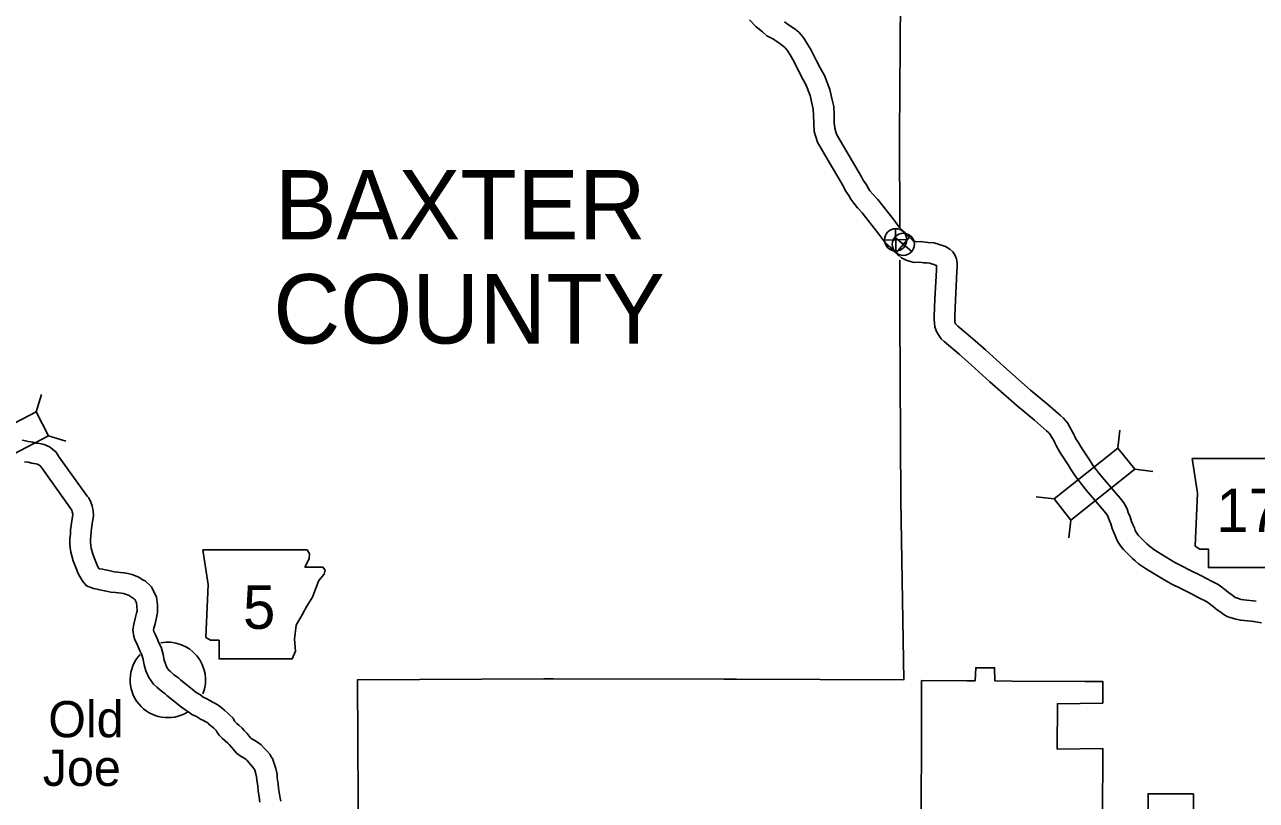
# Model space of a CAD drawing. Extents: x 1377389 to 1380723, y 1168351 to 1170484.
# Drawn here: x 1377653.7 to 1377833.2, y 1170024.2 to 1170137.2 of the extents above; entities that cross this region are included whole.
import ezdxf

# ---------------------------------------------------------------- set-up
doc = ezdxf.new("R2010")
doc.units = 0
doc.layers.add('B_Fill', color=7, linetype='Continuous')
doc.layers.add('Default', color=7, linetype='Continuous')

msp = doc.modelspace()

# ---------------------------------------------------------------- linework, layer by layer
at = {"layer": 'B_Fill'}
for p, q in [((1377780.69, 1170104.22), (1377780.62, 1170107.47)), ((1377779.03, 1170105.81), (1377782.28, 1170105.88)), ((1377780.52, 1170106.25), (1377783.01, 1170104.16)), ((1377780.72, 1170103.96), (1377782.81, 1170106.45)), ((1377655.35, 1170080.79), (1377656.14, 1170083.31)), ((1377813.05, 1170075.51), (1377813.35, 1170078.13)), ((1377657.18, 1170077.28), (1377659.7, 1170076.49)), ((1377815.51, 1170072.41), (1377818.13, 1170072.11)), ((1377803.74, 1170068.12), (1377801.12, 1170068.42)), ((1377806.21, 1170065.02), (1377805.91, 1170062.4))]:
    msp.add_line(p, q, dxfattribs=at)
for points in [[(1377781.38, 1170180.66), (1377781.34, 1170174.2), (1377781.43, 1170147.52), (1377781.22, 1170121.07), (1377781.24, 1170107.61)], [(1377759.33, 1170137.9), (1377760.3, 1170136.87), (1377761.24, 1170136.14), (1377761.9, 1170135.56), (1377762.83, 1170135.08), (1377763.36, 1170134.68), (1377763.76, 1170134.44), (1377764.26, 1170134.09), (1377764.47, 1170133.93), (1377764.57, 1170133.81), (1377764.83, 1170133.5), (1377765.26, 1170132.79), (1377765.69, 1170132.12), (1377766.49, 1170130.5), (1377766.98, 1170129.51), (1377767.57, 1170128.48), (1377768.19, 1170126.88), (1377768.44, 1170125.77), (1377768.65, 1170124.88), (1377768.67, 1170124.02), (1377768.71, 1170122.78), (1377768.8, 1170121.61), (1377769.25, 1170120.06), (1377769.98, 1170118.82), (1377773.04, 1170113.61), (1377773.35, 1170113), (1377773.84, 1170112.3), (1377774.12, 1170111.77), (1377774.54, 1170111.17), (1377775.1, 1170110.53), (1377775.79, 1170109.76), (1377778.04, 1170106.89), (1377778.78, 1170105.89), (1377779.23, 1170105.31), (1377779.92, 1170104.72), (1377780.25, 1170104.35), (1377780.58, 1170104.07), (1377780.97, 1170103.68), (1377781.21, 1170103.49)], [(1377764.43, 1170137.63), (1377765.04, 1170137.18), (1377765.4, 1170136.95), (1377766.06, 1170136.5), (1377766.56, 1170136.09), (1377766.86, 1170135.74), (1377767.28, 1170135.24), (1377767.8, 1170134.38), (1377768.31, 1170133.6), (1377769.17, 1170131.83), (1377769.63, 1170130.93), (1377770.28, 1170129.77), (1377771.06, 1170127.77), (1377771.37, 1170126.44), (1377771.64, 1170125.26), (1377771.67, 1170124.11), (1377771.71, 1170122.95), (1377771.77, 1170122.14), (1377772.03, 1170121.26), (1377772.57, 1170120.34), (1377775.68, 1170115.05), (1377775.93, 1170114.54), (1377776.4, 1170113.88), (1377776.69, 1170113.33), (1377776.91, 1170113.01), (1377777.33, 1170112.52), (1377778.08, 1170111.71), (1377780.43, 1170108.71), (1377781.17, 1170107.71), (1377781.31, 1170107.53)], [(1377781.33, 1170107.5), (1377781.41, 1170107.39), (1377782.02, 1170106.87), (1377782.36, 1170106.49), (1377782.6, 1170106.28), (1377782.98, 1170105.92), (1377783.18, 1170105.75), (1377783.37, 1170105.65), (1377783.48, 1170105.61), (1377783.67, 1170105.56), (1377784.22, 1170105.61), (1377785.02, 1170105.49), (1377785.36, 1170105.47), (1377786.21, 1170105.39), (1377786.74, 1170105.24), (1377787.01, 1170105.15)], [(1377787, 1170105.16), (1377787.9, 1170104.87), (1377788.55, 1170104.5), (1377788.97, 1170104.1), (1377789.28, 1170103.65), (1377789.52, 1170103.06), (1377789.62, 1170102.5), (1377789.63, 1170101.89), (1377789.58, 1170101.25), (1377789.37, 1170097.04), (1377789.27, 1170094.69), (1377789.28, 1170094.28), (1377789.29, 1170093.92), (1377789.3, 1170093.82), (1377789.33, 1170093.75), (1377789.4, 1170093.62), (1377789.53, 1170093.45), (1377789.73, 1170093.27), (1377791.86, 1170091.47), (1377793.73, 1170089.8), (1377796.4, 1170087.39), (1377800.3, 1170083.96), (1377802.85, 1170081.86), (1377804.67, 1170080.25), (1377805.11, 1170079.84), (1377805.38, 1170079.56), (1377805.68, 1170079.16), (1377805.98, 1170078.67), (1377806.29, 1170078.13), (1377806.56, 1170077.6), (1377806.76, 1170077.19), (1377806.94, 1170076.83), (1377807.14, 1170076.51), (1377807.34, 1170076.2), (1377807.59, 1170075.79), (1377807.94, 1170075.26), (1377808.32, 1170074.67), (1377808.79, 1170073.94), (1377809.14, 1170073.38), (1377809.46, 1170072.92), (1377809.83, 1170072.45), (1377810.12, 1170072.06), (1377810.79, 1170071.22), (1377813.37, 1170068.2), (1377813.9, 1170067.53), (1377814.17, 1170067.09), (1377814.38, 1170066.63), (1377814.57, 1170066.13), (1377814.83, 1170065.46), (1377815.05, 1170064.8), (1377815.21, 1170064.39), (1377815.45, 1170063.87), (1377815.58, 1170063.49), (1377815.69, 1170063.27), (1377815.8, 1170063.09), (1377815.91, 1170062.94), (1377816.04, 1170062.78), (1377816.27, 1170062.56), (1377816.75, 1170062.09), (1377817.27, 1170061.57), (1377817.6, 1170061.25), (1377817.85, 1170061.04), (1377818.31, 1170060.73), (1377818.84, 1170060.37), (1377821.36, 1170058.85), (1377822.21, 1170058.39), (1377823.65, 1170057.66), (1377825.16, 1170056.94), (1377826.06, 1170056.44), (1377826.59, 1170056.18), (1377827.1, 1170055.9), (1377827.55, 1170055.65), (1377827.94, 1170055.43), (1377828.45, 1170055.06), (1377828.82, 1170054.76), (1377829.21, 1170054.43), (1377829.46, 1170054.25), (1377829.86, 1170053.96), (1377830.14, 1170053.75), (1377830.18, 1170053.73), (1377830.64, 1170053.6), (1377831.03, 1170053.46), (1377831.43, 1170053.38), (1377833.19, 1170053.21)], [(1377781.29, 1170103.42), (1377781.5, 1170103.24), (1377782.2, 1170102.88), (1377782.61, 1170102.74), (1377783.37, 1170102.53), (1377784.11, 1170102.59), (1377784.74, 1170102.49), (1377785.16, 1170102.48), (1377785.66, 1170102.43), (1377785.88, 1170102.37), (1377786.07, 1170102.3)], [(1377781.25, 1170102.87), (1377781.27, 1170094.83), (1377781.39, 1170067.86), (1377781.87, 1170041.74), (1377757.45, 1170041.84), (1377755.62, 1170041.82), (1377730.78, 1170041.9), (1377729.39, 1170041.87), (1377702.21, 1170041.75), (1377702.36, 1170015.31), (1377702.37, 1170011.92)], [(1377786.09, 1170102.3), (1377786.63, 1170102.13), (1377786.63, 1170101.97), (1377786.59, 1170101.44), (1377786.37, 1170097.18), (1377786.27, 1170094.71), (1377786.29, 1170094.2), (1377786.3, 1170093.76), (1377786.35, 1170093.16), (1377786.6, 1170092.49), (1377786.88, 1170091.98), (1377787.31, 1170091.42), (1377787.75, 1170091.02), (1377789.9, 1170089.2), (1377791.73, 1170087.57), (1377794.4, 1170085.15), (1377798.35, 1170081.67), (1377800.91, 1170079.57), (1377802.66, 1170078.03), (1377803, 1170077.71), (1377803.08, 1170077.63), (1377803.2, 1170077.47), (1377803.39, 1170077.15), (1377803.65, 1170076.69), (1377803.88, 1170076.26), (1377804.06, 1170075.87), (1377804.32, 1170075.36), (1377804.61, 1170074.9), (1377804.8, 1170074.6), (1377805.07, 1170074.17), (1377805.43, 1170073.63), (1377805.8, 1170073.04), (1377806.26, 1170072.33), (1377806.64, 1170071.73), (1377807.05, 1170071.14), (1377807.44, 1170070.64), (1377807.73, 1170070.24), (1377808.47, 1170069.31), (1377811.06, 1170066.29), (1377811.43, 1170065.82), (1377811.52, 1170065.67), (1377811.62, 1170065.45), (1377811.77, 1170065.06), (1377812.01, 1170064.46), (1377812.22, 1170063.79), (1377812.45, 1170063.21), (1377812.67, 1170062.74), (1377812.8, 1170062.36), (1377813.05, 1170061.83), (1377813.31, 1170061.4), (1377813.56, 1170061.07), (1377813.86, 1170060.72), (1377814.18, 1170060.41), (1377814.64, 1170059.96), (1377815.17, 1170059.43), (1377815.56, 1170059.05), (1377816.03, 1170058.64), (1377816.64, 1170058.24), (1377817.21, 1170057.84), (1377819.87, 1170056.25), (1377820.82, 1170055.73), (1377822.33, 1170054.97), (1377823.78, 1170054.27), (1377824.67, 1170053.78), (1377825.22, 1170053.51), (1377825.67, 1170053.27), (1377826.09, 1170053.03), (1377826.31, 1170052.91), (1377826.61, 1170052.68), (1377826.92, 1170052.44), (1377827.34, 1170052.08), (1377827.69, 1170051.82), (1377828.08, 1170051.55), (1377828.53, 1170051.2), (1377829.08, 1170050.92), (1377829.75, 1170050.73), (1377830.22, 1170050.57), (1377830.97, 1170050.41), (1377832.91, 1170050.23)], [(1377653.33, 1170076.64), (1377653.79, 1170076.55), (1377654.19, 1170076.47), (1377654.86, 1170076.38), (1377655.36, 1170076.23), (1377655.84, 1170076.17), (1377656.55, 1170076), (1377657.32, 1170075.66), (1377658.23, 1170074.94), (1377658.73, 1170074.2), (1377662.81, 1170068.48), (1377663.05, 1170068.26), (1377663.36, 1170067.64), (1377663.53, 1170067.08), (1377663.56, 1170066.78), (1377663.67, 1170066.39), (1377663.73, 1170065.63), (1377663.59, 1170064.78), (1377663.45, 1170063.77), (1377663.38, 1170063.29), (1377663.36, 1170062.73), (1377663.29, 1170062.14), (1377663.29, 1170061.72), (1377663.32, 1170061.3), (1377663.38, 1170060.94), (1377663.61, 1170060.04), (1377664.08, 1170058.92), (1377664.24, 1170058.46), (1377664.37, 1170058.18), (1377664.51, 1170057.94), (1377664.51, 1170057.94), (1377664.55, 1170057.92), (1377665.03, 1170057.85), (1377665.49, 1170057.74), (1377665.97, 1170057.64), (1377666.74, 1170057.49), (1377667.25, 1170057.42), (1377667.66, 1170057.38), (1377668.15, 1170057.34), (1377668.75, 1170057.24), (1377669.36, 1170057.06), (1377669.95, 1170056.82), (1377670.34, 1170056.69), (1377670.99, 1170056.25), (1377671.24, 1170056.14), (1377672.17, 1170055.29), (1377672.59, 1170054.48), (1377672.91, 1170053.83), (1377673.04, 1170052.68), (1377673.07, 1170051.52), (1377672.93, 1170050.8), (1377672.7, 1170049.9), (1377672.53, 1170049.24), (1377672.49, 1170049.03), (1377672.54, 1170048.74), (1377672.55, 1170048.69), (1377672.75, 1170048.29), (1377672.99, 1170047.75), (1377673.27, 1170047.12), (1377673.58, 1170046.47), (1377673.89, 1170045.41), (1377674.05, 1170044.58), (1377674.2, 1170044.05), (1377674.42, 1170043.54), (1377674.7, 1170043.14), (1377674.93, 1170042.94), (1377675.46, 1170042.47), (1377676.1, 1170042.02), (1377676.42, 1170041.71), (1377678.38, 1170040.13), (1377678.69, 1170039.9), (1377679.33, 1170039.53), (1377679.7, 1170039.23), (1377680.15, 1170039.01), (1377680.76, 1170038.65), (1377681.19, 1170038.44)], [(1377653.68, 1170073.52), (1377654.22, 1170073.44), (1377654.76, 1170073.28), (1377655.3, 1170073.22), (1377655.58, 1170073.15), (1377655.77, 1170073.06), (1377656.01, 1170072.87), (1377656.27, 1170072.49), (1377660.55, 1170066.47), (1377660.58, 1170066.45), (1377660.61, 1170066.2), (1377660.7, 1170065.87), (1377660.71, 1170065.76), (1377660.62, 1170065.23), (1377660.49, 1170064.21), (1377660.38, 1170063.59), (1377660.36, 1170062.95), (1377660.29, 1170062.31), (1377660.29, 1170061.61), (1377660.34, 1170060.96), (1377660.44, 1170060.33), (1377660.76, 1170059.07), (1377661.27, 1170057.86), (1377661.45, 1170057.32), (1377661.71, 1170056.79), (1377662.05, 1170056.2), (1377662.7, 1170055.45), (1377663.71, 1170055.02), (1377664.47, 1170054.9), (1377664.83, 1170054.82), (1377665.36, 1170054.7), (1377666.27, 1170054.52), (1377666.92, 1170054.44), (1377667.37, 1170054.4), (1377667.77, 1170054.36), (1377668.09, 1170054.31), (1377668.37, 1170054.23), (1377668.92, 1170054), (1377668.99, 1170053.98), (1377669.54, 1170053.6), (1377669.61, 1170053.58), (1377669.75, 1170053.44), (1377669.91, 1170053.13), (1377669.99, 1170052.97), (1377670.05, 1170052.47), (1377670.07, 1170051.77), (1377670, 1170051.46), (1377669.8, 1170050.66), (1377669.59, 1170049.86), (1377669.46, 1170049.02), (1377669.61, 1170048.03), (1377669.77, 1170047.56), (1377670.03, 1170047.03), (1377670.25, 1170046.53), (1377670.55, 1170045.85), (1377670.77, 1170045.39), (1377670.97, 1170044.71), (1377671.12, 1170043.9), (1377671.36, 1170043.06), (1377671.79, 1170042.06), (1377672.46, 1170041.11), (1377672.95, 1170040.68), (1377673.61, 1170040.11), (1377674.18, 1170039.7), (1377674.43, 1170039.46), (1377676.53, 1170037.76), (1377677.03, 1170037.39), (1377677.64, 1170037.04), (1377678.08, 1170036.69), (1377678.72, 1170036.37), (1377679.34, 1170036), (1377679.87, 1170035.75)], [(1377833.98, 1170050.06), (1377832.83, 1170050.24)], [(1377810.79, 1170018.55), (1377810.82, 1170025.15), (1377810.83, 1170028.2), (1377810.84, 1170031.75), (1377804.22, 1170031.64), (1377804.24, 1170038.24), (1377810.85, 1170038.35), (1377810.86, 1170041.48), (1377808.21, 1170041.49), (1377797.65, 1170041.55), (1377795.12, 1170041.57), (1377795.08, 1170043.5), (1377792.33, 1170043.5), (1377792.24, 1170041.59), (1377791.05, 1170041.59), (1377784.44, 1170041.63), (1377784.4, 1170031.33), (1377784.36, 1170024.73), (1377784.32, 1170018.13)], [(1377681.23, 1170038.42), (1377681.75, 1170038.14), (1377682.26, 1170037.8), (1377682.62, 1170037.45), (1377682.85, 1170037.27), (1377683.32, 1170036.89), (1377683.62, 1170036.58), (1377684.07, 1170036.13), (1377684.29, 1170035.7), (1377684.31, 1170035.67), (1377684.6, 1170035.36), (1377684.89, 1170035.11), (1377685.38, 1170034.68), (1377685.71, 1170034.35), (1377686.12, 1170033.89), (1377686.41, 1170033.54), (1377686.67, 1170033.24), (1377686.81, 1170033.13), (1377687.26, 1170032.87), (1377687.61, 1170032.64), (1377688.15, 1170032.26), (1377688.6, 1170031.76), (1377688.88, 1170031.48), (1377689.48, 1170030.87), (1377689.59, 1170030.54), (1377689.81, 1170030.28), (1377690.06, 1170029.55), (1377690.3, 1170028.82), (1377690.49, 1170027.99), (1377690.51, 1170027.46), (1377690.65, 1170026.57), (1377690.7, 1170025.93), (1377690.85, 1170025.06), (1377690.92, 1170024.47), (1377691.03, 1170024.05)], [(1377679.82, 1170035.77), (1377680.21, 1170035.57), (1377680.37, 1170035.46), (1377680.64, 1170035.19), (1377680.98, 1170034.92), (1377681.29, 1170034.67), (1377681.47, 1170034.49), (1377681.61, 1170034.35), (1377681.76, 1170034.05), (1377682.06, 1170033.68), (1377682.52, 1170033.2), (1377682.91, 1170032.86), (1377683.33, 1170032.49), (1377683.52, 1170032.29), (1377683.85, 1170031.92), (1377684.13, 1170031.59), (1377684.59, 1170031.07), (1377685.12, 1170030.64), (1377685.68, 1170030.32), (1377685.91, 1170030.17), (1377686.07, 1170030.05), (1377687.16, 1170028.77), (1377687.22, 1170028.59), (1377687.4, 1170028.02), (1377687.5, 1170027.6), (1377687.52, 1170027.16), (1377687.67, 1170026.22), (1377687.72, 1170025.55), (1377687.88, 1170024.62), (1377687.97, 1170023.91)], [(1377824.05, 1170018.52), (1377824.07, 1170025.12), (1377817.44, 1170025.13), (1377817.42, 1170018.54)]]:
    msp.add_lwpolyline(points, dxfattribs=at)
for points in [[(1377655.35, 1170080.79), (1377644.81, 1170075.31), (1377646.64, 1170071.8), (1377657.18, 1170077.28)], [(1377813.05, 1170075.51), (1377803.74, 1170068.12), (1377806.21, 1170065.02), (1377815.51, 1170072.41)], [(1377823.87, 1170073.99), (1377824.63, 1170068.91), (1377824.29, 1170061.22), (1377824.97, 1170060.79), (1377826.24, 1170060.79), (1377826.24, 1170058.09), (1377836.9, 1170058.09), (1377837.4, 1170059.19), (1377837.23, 1170060.96), (1377837.49, 1170062.99), (1377838.42, 1170064.6), (1377839.01, 1170065.78), (1377839.86, 1170067.05), (1377840.36, 1170068.41), (1377840.79, 1170069.51), (1377841.55, 1170070.44), (1377841.72, 1170071.03), (1377841.38, 1170071.45), (1377838.76, 1170071.45), (1377839.35, 1170072.64), (1377839.43, 1170073.4), (1377839.08, 1170073.98)], [(1377679.66, 1170060.69), (1377680.42, 1170055.62), (1377680.08, 1170047.92), (1377680.76, 1170047.5), (1377682.03, 1170047.5), (1377682.03, 1170044.79), (1377692.69, 1170044.79), (1377693.19, 1170045.89), (1377693.02, 1170047.66), (1377693.28, 1170049.69), (1377694.21, 1170051.3), (1377694.8, 1170052.49), (1377695.65, 1170053.76), (1377696.15, 1170055.11), (1377696.58, 1170056.21), (1377697.34, 1170057.14), (1377697.51, 1170057.73), (1377697.17, 1170058.15), (1377694.55, 1170058.15), (1377695.14, 1170059.34), (1377695.22, 1170060.1), (1377694.87, 1170060.68)]]:
    msp.add_lwpolyline(points, close=True, dxfattribs=at)
for centre, radius in [((1377780.66, 1170105.84), 1.63), ((1377781.77, 1170105.2), 1.62)]:
    msp.add_circle(centre, radius, dxfattribs=at)
for start, end in [(338.518, 100.8987), (137.4681, 301.4462)]:
    msp.add_arc((1377674.56, 1170041.72), 5.5, start, end, dxfattribs=at)

# ---------------------------------------------------------------- texts
for s, height, p in [('177', 6.336, (1377827.39, 1170063.25)), ('5', 6.34, (1377685.52, 1170049.16)), ('Old', 5.28, (1377657.13, 1170033.36)), ('Joe', 5.28, (1377656.33, 1170026.27))]:
    msp.add_text(s, height=height, dxfattribs=at).set_placement(p)
at = {"layer": 'Default'}
for s, p in [('BAXTER', (1377690.15, 1170105.9)), ('COUNTY', (1377689.93, 1170090.74))]:
    msp.add_text(s, height=10.107, rotation=360, dxfattribs=at).set_placement(p)

doc.saveas('drawing.dxf')
